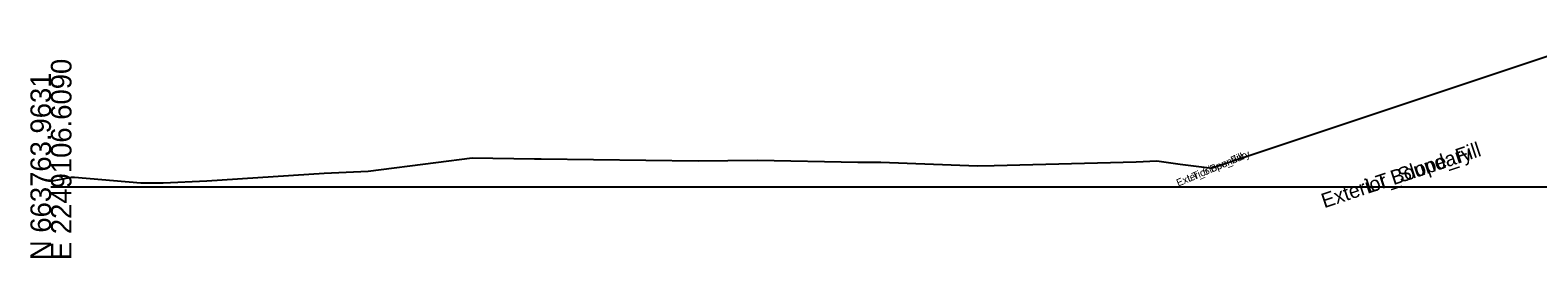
# Model space of a CAD drawing. Extents: x -26 to 2603, y -10 to 9566.
# Drawn here: x 997.2 to 1203, y 6990.3 to 7021.4 of the extents above; entities that cross this region are included whole.
import ezdxf

# ---------------------------------------------------------------- set-up
doc = ezdxf.new("R2010")
doc.units = 0
for name, color, linetype in [('Default', 7, 'Continuous'), ('Exist Cross Section Cell', 7, 'Continuous'), ('Exist XS Ground Line', 7, 'Continuous'), ('Scratch_Level_9', 7, 'Continuous')]:
    doc.layers.add(name, color=color, linetype=linetype)

msp = doc.modelspace()

# ---------------------------------------------------------------- linework, layer by layer
at = {"layer": 'Exist Cross Section Cell'}
msp.add_line((1000, 7000), (1300, 7000), dxfattribs=at)
at = {"layer": 'Exist XS Ground Line'}
for p, q in [((1043.32, 7002.12), (1052.53, 7003.3)), ((1052.53, 7003.3), (1057.49, 7003.96)), ((1057.49, 7003.96), (1066.04, 7003.82)), ((1066.04, 7003.82), (1066.44, 7003.82)), ((1066.44, 7003.82), (1066.91, 7003.82)), ((1066.91, 7003.82), (1088.38, 7003.57)), ((1088.38, 7003.57), (1096.47, 7003.64)), ((1096.47, 7003.64), (1110.15, 7003.36)), ((1110.15, 7003.36), (1113.3, 7003.37)), ((1113.3, 7003.37), (1126.49, 7002.86)), ((1128.77, 7002.92), (1148.16, 7003.43)), ((1148.16, 7003.43), (1151, 7003.53)), ((1151, 7003.53), (1154.16, 7003.09)), ((1154.16, 7003.09), (1158.55, 7002.55)), ((1000, 7000.77), (1002.79, 7001.32)), ((1002.79, 7001.32), (1003.2, 7001.33)), ((1003.2, 7001.33), (1012.27, 7000.56)), ((1021.28, 7000.81), (1037.3, 7001.88)), ((1037.3, 7001.88), (1043.32, 7002.12)), ((1126.49, 7002.86), (1128.77, 7002.92)), ((1012.27, 7000.56), (1015.34, 7000.54)), ((1015.34, 7000.54), (1021.28, 7000.81))]:
    msp.add_line(p, q, dxfattribs=at)
msp.add_lwpolyline([(1215.05, 7021.39), (1158.55, 7002.55)], dxfattribs=at)

# ---------------------------------------------------------------- texts
at = {"layer": 'Default'}
msp.add_text('-', height=0.0001, dxfattribs=at).set_placement((1000, 7000))
msp.add_text('-', height=0.0001, dxfattribs=at).set_placement((1000, 7000))
msp.add_text('-', height=0.0001, dxfattribs=at).set_placement((1000, 7000))
msp.add_text('-', height=0.0001, dxfattribs=at).set_placement((1000, 7000))
msp.add_text('-', height=0.0001, dxfattribs=at).set_placement((1000, 7000))
at = {"layer": 'Exist Cross Section Cell'}
for s, p in [('N 663763.9631', (1000, 6990)), ('E 2249106.6090', (1002.8, 6990))]:
    msp.add_text(s, height=2.8, rotation=90, dxfattribs=at).set_placement(p)
at = {"layer": 'Scratch_Level_9'}
for s, height, rotation, p in [('Exterior Boundary', 2, 18.4332, (1173.85, 6997.07)), ('LT_Slope_Fill', 2, 18.4332, (1179.9, 6999.09)), ('Exterior Boundary', 1, 22.5575, (1153.91, 7000.03)), ('Exterior Boundary', 1, 22.5575, (1153.91, 7000.03)), ('LT_Slope_Fill', 1, 22.5575, (1155.36, 7000.64)), ('LT_Slope_Fill', 1, 22.5575, (1155.36, 7000.64))]:
    msp.add_text(s, height=height, rotation=rotation, dxfattribs=at).set_placement(p)

doc.saveas('drawing.dxf')
